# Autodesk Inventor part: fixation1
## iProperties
Created: 2002-09
Part Number: fixation1
Material: Par défaut
Document SubType Name: Modélisation
Designer: Maison
Control State: 0
Master: False
Checked Out: False
Shininess: 27.0
Length Units: 11269
Angle Units: 11279
Time Units: 11290
Mass Units: 11283
Length Display Precision: 3
Angle Display Precision: 2
Density: 0.0
Volumn: 0.0
Area: 0.0
PropertySet Name: Model Information
Author: Maison
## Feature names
1. Extrusion1
2. Congé1 [Fillet]
3. Perçage1 [Hole]
4. Extrusion4
5. Extrusion5
6. Congé4 [Fillet]
7. Extrusion6
8. Révolution2 [Revolution]
9. Révolution4 [Revolution]
10. Congé6 [Fillet]
